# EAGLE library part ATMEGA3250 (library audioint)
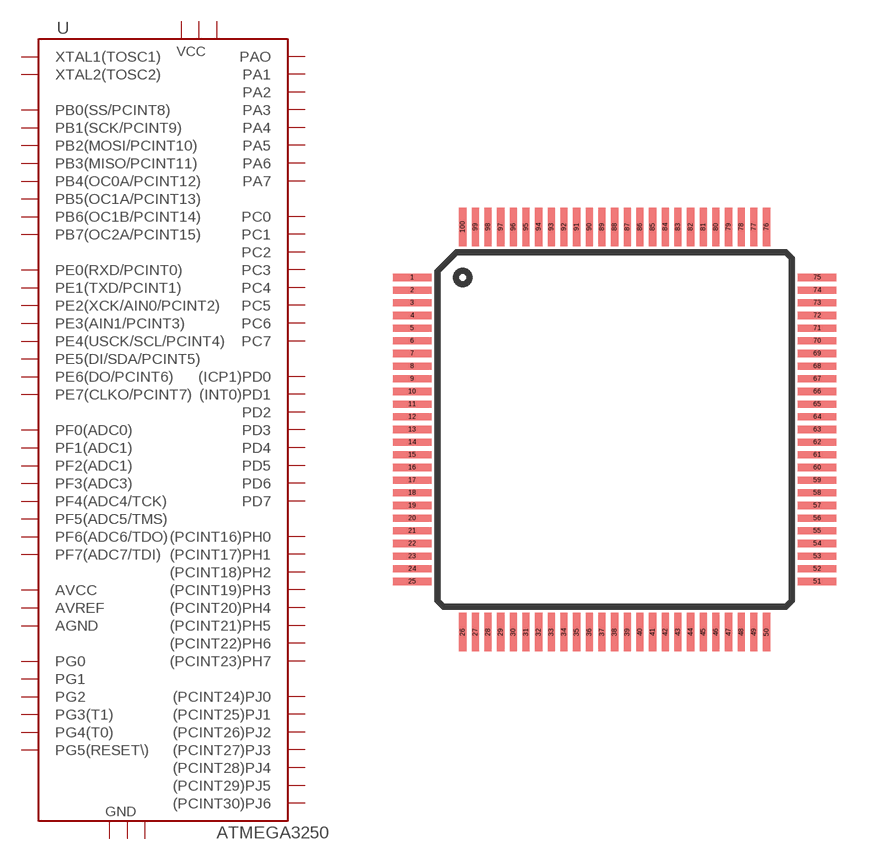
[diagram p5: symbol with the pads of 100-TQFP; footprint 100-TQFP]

Designator prefix -

## ATMEGA3250100-TQFP  [100-TQFP]
2  PE0(RXD/PCINT0)
3  PE1(TXD/PCINT1)
4  PE2(XCK/AIN0/PCINT2)
5  PE3(AIN1/PCINT3)
6  PE4(USCK/SCL/PCINT4)
7  PE5(DI/SDA/PCINT5)
8  PE6(DO/PCINT6)
9  PE7(CLKO/PCINT7)
10  03  pwr
11  04  pwr
13  (PCINT24)PJ0
14  (PCINT25)PJ1
19  PB0(SS/PCINT8)
20  PB1(SCK/PCINT9)
21  PB2(MOSI/PCINT10)
22  PB3(MISO/PCINT11)
23  PB4(OC0A/PCINT12)
24  PB5(OC1A/PCINT13)
25  PB6(OC1B/PCINT14)
26  PB7(OC2A/PCINT15)
28  PG3(T1)
29  PG4(T0)
30  PG5(RESET\)
31  VCC  pwr
32  GND  pwr
33  XTAL2(TOSC2)
34  XTAL1(TOSC1)
37  (PCINT26)PJ2
38  (PCINT27)PJ3
39  (PCINT28)PJ4
40  (PCINT29)PJ5
41  (PCINT30)PJ6
43  (ICP1)PD0
44  (INT0)PD1
45  PD2
46  PD3
47  PD4
48  PD5
49  PD6
50  PD7
51  PG0
52  PG1
53  PC0
54  PC1
55  PC2
56  PC3
57  PC4
58  PC5
63  (PCINT16)PH0
64  (PCINT17)PH1
65  (PCINT18)PH2
66  (PCINT19)PH3
68  PC6
69  PC7
70  PG2
71  PA7
72  PA6
73  PA5
74  PA4
75  PA3
76  PA2
77  PA1
78  PAO
80  01  pwr
81  02  pwr
84  (PCINT20)PH4
85  (PCINT21)PH5
86  (PCINT22)PH6
87  (PCINT23)PH7
90  PF7(ADC7/TDI)
91  PF6(ADC6/TDO)
92  PF5(ADC5/TMS)
93  PF4(ADC4/TCK)
94  PF3(ADC3)
95  PF2(ADC1)
96  PF1(ADC1)
97  PF0(ADC0)
98  AVREF
99  AGND  pwr
100  AVCC  pwr

## Footprint 100-TQFP (pad centres in mm)
smd 1.524 x 0.279: 1 -8,6; 2 -8,5.5; 3 -8,5; 4 -8,4.5; 5 -8,4; 6 -8,3.5; 7 -8,3; 8 -8,2.5; 9 -8,2; 10 -8,1.5; 11 -8,1; 12 -8,0.5; 13 -8,0; 14 -8,-0.5; 15 -8,-1; 16 -8,-1.5; 17 -8,-2; 18 -8,-2.5; 19 -8,-3; 20 -8,-3.5; 21 -8,-4; 22 -8,-4.5; 23 -8,-5; 24 -8,-5.5; 25 -8,-6; 51 8,-6; 52 8,-5.5; 53 8,-5; 54 8,-4.5; 55 8,-4; 56 8,-3.5; 57 8,-3; 58 8,-2.5; 59 8,-2; 60 8,-1.5; 61 8,-1; 62 8,-0.5; 63 8,0; 64 8,0.5; 65 8,1; 66 8,1.5; 67 8,2; 68 8,2.5; 69 8,3; 70 8,3.5; 71 8,4; 72 8,4.5; 73 8,5; 74 8,5.5; 75 8,6
smd 0.279 x 1.524: 26 -6,-8; 27 -5.5,-8; 28 -5,-8; 29 -4.5,-8; 30 -4,-8; 31 -3.5,-8; 32 -3,-8; 33 -2.5,-8; 34 -2,-8; 35 -1.5,-8; 36 -1,-8; 37 -0.5,-8; 38 0,-8; 39 0.5,-8; 40 1,-8; 41 1.5,-8; 42 2,-8; 43 2.5,-8; 44 3,-8; 45 3.5,-8; 46 4,-8; 47 4.5,-8; 48 5,-8; 49 5.5,-8; 50 6,-8; 76 6,8; 77 5.5,8; 78 5,8; 79 4.5,8; 80 4,8; 81 3.5,8; 82 3,8; 83 2.5,8; 84 2,8; 85 1.5,8; 86 1,8; 87 0.5,8; 88 0,8; 89 -0.5,8; 90 -1,8; 91 -1.5,8; 92 -2,8; 93 -2.5,8; 94 -3,8; 95 -3.5,8; 96 -4,8; 97 -4.5,8; 98 -5,8; 99 -5.5,8; 100 -6,8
